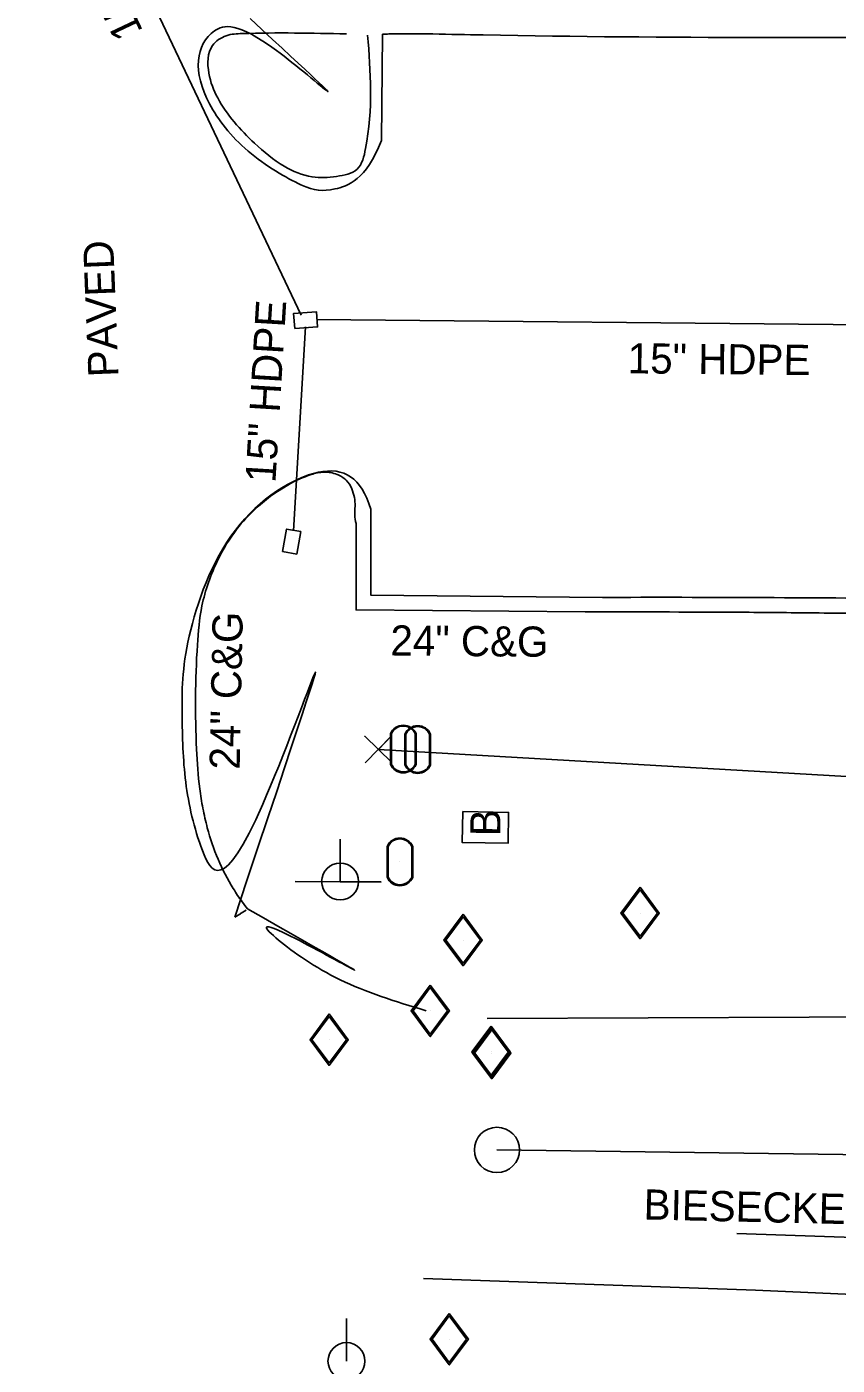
# Model space of a CAD drawing. Extents: x 1627482 to 1629573, y 760826 to 766301.
# Drawn here: x 1628089.7 to 1628197, y 764811 to 764988.4 of the extents above; entities that cross this region are included whole.
import ezdxf

# ---------------------------------------------------------------- set-up
doc = ezdxf.new("R2010")
doc.units = 0
for name, color, linetype in [('Default', 7, 'Continuous'), ('Exist Building', 7, 'Continuous'), ('Exist Building Text', 7, 'Continuous'), ('Exist Horizontal Alignment', 7, 'Continuous'), ('Exist Horizontal Alignment Point', 7, 'Continuous'), ('Exist Property Corner CELL', 7, 'Continuous'), ('Exist Right of Way Line', 7, 'Continuous'), ('Exist Roads Curbs', 7, 'Continuous'), ('Exist Roads Curbs Text', 7, 'Continuous'), ('Exist Roads EOP', 7, 'Continuous'), ('Exist Roads EOP Other', 7, 'Continuous'), ('Exist Roads EOP Text', 7, 'Continuous'), ('Exist Structure Minor Drop Inlet', 7, 'Continuous'), ('Exist Structure Minor Pipes HDPE 15 Inch', 7, 'Continuous'), ('Exist Structure Minor Pipes HDPE 15 Inch Text', 7, 'Continuous'), ('Exist Utilities Gas Valve CELL', 7, 'Continuous'), ('Exist Utilities Power Joint Use Telephone CELL', 7, 'Continuous'), ('Exist Utilities Power Pole CELL', 7, 'Continuous'), ('Exist Utilities Water Meter CELL', 7, 'Continuous'), ('Exist Utilities Water UG Line SUE LOS B', 7, 'Continuous')]:
    doc.layers.add(name, color=color, linetype=linetype)

# ---------------------------------------------------------------- blocks, each defined once
blk = doc.blocks.new('POINT_DISPLAY')
at = {"layer": 'Default'}
blk.add_line((0, 0), (0, 0), dxfattribs=at)
blk = doc.blocks.new('EXIST PROPERTY CORNER')
at = {"layer": 'Exist Property Corner CELL'}
blk.add_lwpolyline([(-3.809999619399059, -2.079104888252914e-10), (3.809999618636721, -6.930349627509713e-11), (-3.8116922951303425e-10, -2.079104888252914e-10), (-3.8116922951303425e-10, 3.8099996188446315), (-3.4651748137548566e-10, -3.8099996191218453)], dxfattribs=at)
blk.add_blockref('POINT_DISPLAY', (-3.8116922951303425e-10, -2.079104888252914e-10), dxfattribs=at)

msp = doc.modelspace()

# ---------------------------------------------------------------- linework, layer by layer
at = {"layer": 'Exist Building'}
msp.add_lwpolyline([(1628147.416, 764884.4049999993), (1628147.332230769, 764880.3054786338), (1628153.424, 764880.1809999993), (1628153.5077692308, 764884.2805213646)], close=True, dxfattribs=at)
at = {"layer": 'Exist Horizontal Alignment'}
msp.add_line((1628151.9601007, 764839.55444704), (1628347.9286044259, 764837.0098619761), dxfattribs=at)
at = {"layer": 'Exist Horizontal Alignment Point'}
msp.add_circle((1628151.9601007, 764839.55444704), 3, dxfattribs=at)
at = {"layer": 'Exist Right of Way Line'}
msp.add_lwpolyline([(1628316.1367612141, 764882.2173325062), (1628136.2421493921, 764892.6224989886)], dxfattribs=at)
at = {"layer": 'Exist Roads Curbs'}
msp.add_lwpolyline([(1628163.622, 764910.8479999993), (1628133.295, 764911.1149999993), (1628133.315, 764922.5549999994)], dxfattribs=at)
for points in [[(1628132.02, 764987.433), (1628118.222, 764987.484), (1628116.098, 764987.2000000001), (1628114.286, 764985.9180000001), (1628113.795, 764982.2170000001), (1628114.956, 764978.959), (1628119.848, 764972.947), (1628123.7480000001, 764969.898), (1628127.475, 764968.4940000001), (1628130.7040000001, 764968.558), (1628133.432, 764969.519), (1628134.551, 764972.2390000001), (1628134.824, 764987.289)], [(1628133.315, 764922.5549999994), (1628133.315, 764922.555), (1628133.155739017, 764924.853950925), (1628132.7310000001, 764927.147), (1628131.97615504, 764928.3054287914), (1628131.4102955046, 764928.735390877), (1628130.773, 764929.064), (1628129.0438645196, 764929.3706454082), (1628127.338, 764929.0480000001), (1628124.254, 764927.656), (1628119.86, 764924.414), (1628117.539, 764921.877), (1628114.955, 764917.675), (1628112.878, 764911.652), (1628112.27, 764906.471), (1628112.1570000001, 764892.64), (1628112.5772341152, 764887.4170483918), (1628112.9966976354, 764884.8213406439), (1628113.582, 764882.234), (1628115.0103715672, 764878.0750392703), (1628117.031, 764874.182), (1628118.214, 764872.4130000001), (1628118.906, 764871.5160000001)], [(1628269.175, 764910.371), (1628265.0624914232, 764910.1381060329), (1628260.9478245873, 764909.9719178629), (1628252.7204506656, 764909.7939625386), (1628236.265318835, 764909.9030827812), (1628219.8102442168, 764910.250166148), (1628203.355, 764910.593), (1628193.4221753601, 764910.7213471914), (1628183.488812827, 764910.801801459), (1628163.622, 764910.848)]]:
    msp.add_spline(points, degree=3, dxfattribs=at)
at = {"layer": 'Exist Roads EOP'}
for points in [[(1628150.643, 764856.9707), (1628193.332, 764857.133), (1628234.415, 764857.3713), (1628279.409, 764859.144), (1628289.419, 764861.2023), (1628302.9987823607, 764867.7237944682), (1628311.854, 764876.0147), (1628320.150910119, 764886.5805522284)], [(1628142.235, 764822.5291), (1628186.2280000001, 764820.9717000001), (1628230.891, 764818.9683), (1628274.652, 764816.7169), (1628294.4581179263, 764813.5617935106), (1628307.6638003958, 764807.3062263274), (1628315.974, 764801.5203), (1628323.4286103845, 764792.9474789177), (1628330.18, 764781.1492), (1628330.009, 764780.2597), (1628331.176, 764769.0084000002), (1628332.004, 764752.6177)]]:
    msp.add_lwpolyline(points, dxfattribs=at)
at = {"layer": 'Exist Roads EOP Other'}
msp.add_line((1628136.8090000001, 764987.3959999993), (1628136.654, 764973.2969999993), dxfattribs=at)
msp.add_lwpolyline([(1628165.9408687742, 764912.7661292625), (1628135.2550000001, 764913.0519999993), (1628135.235, 764924.4619999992)], dxfattribs=at)
for points in [[(1628136.654, 764973.2969999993), (1628134.628, 764968.0609999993), (1628129.739, 764966.4649999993), (1628126.911, 764966.6649999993), (1628118.441, 764971.6299999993), (1628113.251, 764978.3049999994), (1628111.798, 764984.2019999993), (1628114.026, 764988.3279999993), (1628119.266, 764989.4709999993), (1628136.654, 764973.2969999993), (1628119.266, 764989.4709999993)], [(1628135.235, 764924.4619999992), (1628133.9880000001, 764928.6819999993), (1628129.374, 764931.4219999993), (1628116.056, 764923.0979999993), (1628110.215, 764906.3789999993), (1628110.214, 764897.2549999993), (1628110.411, 764888.3449999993), (1628112.495, 764879.1489999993), (1628117.2280000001, 764870.4139999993), (1628135.235, 764924.4619999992), (1628117.2280000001, 764870.4139999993)], [(1628118.735, 764871.3099999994), (1628117.2280000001, 764870.4139999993), (1628118.735, 764871.3099999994), (1628117.2280000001, 764870.4139999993)], [(1628142.562, 764857.9979999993), (1628138.443, 764859.2249999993), (1628130.689, 764861.7249999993), (1628122.125, 764867.7459999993), (1628118.906, 764871.5159999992), (1628142.562, 764857.9979999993), (1628118.906, 764871.5159999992)]]:
    msp.add_open_spline(points, degree=3, dxfattribs=at)
for points in [[(1628267.787, 764986.6680000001), (1628256.7183733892, 764986.9814808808), (1628245.6494205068, 764987.0589539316), (1628223.511, 764987.018), (1628150.134, 764987.297), (1628143.4713701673, 764987.426266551), (1628140.140129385, 764987.4655002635), (1628138.4745478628, 764987.4486450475), (1628137.6417693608, 764987.4273341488), (1628136.8090000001, 764987.3960000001)], [(1628165.9408687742, 764912.7661292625), (1628169.68, 764912.7760000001), (1628213.124, 764912.577), (1628267.2210000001, 764912.323)]]:
    msp.add_spline(points, degree=3, dxfattribs=at)
at = {"layer": 'Exist Structure Minor Drop Inlet'}
for points in [[(1628125.1600000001, 764948.4009999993), (1628128.196240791, 764948.6099720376), (1628128.0590000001, 764950.6039999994), (1628125.0227592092, 764950.395027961)], [(1628123.5420000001, 764918.8509999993), (1628125.4286855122, 764918.5114160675), (1628125.963, 764921.4799999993), (1628124.076314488, 764921.8195839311)]]:
    msp.add_lwpolyline(points, close=True, dxfattribs=at)
at = {"layer": 'Exist Structure Minor Pipes HDPE 15 Inch'}
for p, q in [((1628082.516382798, 765041.8879629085), (1628125.9995884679, 764950.1560554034)), ((1628128.0586537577, 764949.607678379), (1628235.286423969, 764948.5760348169)), ((1628124.9800509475, 764921.5784282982), (1628126.6016877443, 764948.6013431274))]:
    msp.add_line(p, q, dxfattribs=at)
at = {"layer": 'Exist Utilities Gas Valve CELL'}
for p, q in [((1628170.92, 764870.9419999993), (1628170.92, 764870.9419999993)), ((1628147.467, 764867.3649999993), (1628147.467, 764867.3649999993)), ((1628143.122, 764857.9829999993), (1628143.122, 764857.9829999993)), ((1628129.727, 764854.1619999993), (1628129.727, 764854.1619999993)), ((1628151.187, 764852.5359999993), (1628151.187, 764852.5359999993)), ((1628151.271, 764852.3929), (1628151.271, 764852.3929)), ((1628145.644, 764814.4753), (1628145.644, 764814.4753))]:
    msp.add_line(p, q, dxfattribs=at)
for points in [[(1628170.92, 764874.3544999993), (1628168.3825, 764870.9419999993), (1628170.92, 764867.5294999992), (1628173.4575, 764870.9419999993), (1628170.92, 764874.3544999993)], [(1628147.467, 764870.7774999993), (1628144.9295, 764867.3649999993), (1628147.467, 764863.9524999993), (1628150.0045, 764867.3649999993), (1628147.467, 764870.7774999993)], [(1628143.122, 764861.3954999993), (1628140.5845, 764857.9829999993), (1628143.122, 764854.5704999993), (1628145.6595, 764857.9829999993), (1628143.122, 764861.3954999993)], [(1628129.727, 764857.5744999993), (1628127.1895, 764854.1619999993), (1628129.727, 764850.7494999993), (1628132.2645, 764854.1619999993), (1628129.727, 764857.5744999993)], [(1628151.187, 764855.9484999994), (1628148.6495, 764852.5359999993), (1628151.187, 764849.1234999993), (1628153.7245, 764852.5359999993), (1628151.187, 764855.9484999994)], [(1628151.271, 764855.8054), (1628148.7335, 764852.3929), (1628151.271, 764848.9804), (1628153.8085, 764852.3929), (1628151.271, 764855.8054)], [(1628145.644, 764817.8878000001), (1628143.1065, 764814.4753), (1628145.644, 764811.0628000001), (1628148.1815, 764814.4753), (1628145.644, 764817.8878000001)]]:
    msp.add_lwpolyline(points, dxfattribs=at)
for points in [[(1628173.2082671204, 764870.9419999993), (1628170.92, 764874.0193247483), (1628168.6317328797, 764870.9419999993), (1628170.92, 764867.8646752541)], [(1628149.7552671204, 764867.3649999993), (1628147.467, 764870.4423247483), (1628145.1787328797, 764867.3649999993), (1628147.467, 764864.2876752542)], [(1628145.4102671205, 764857.9829999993), (1628143.122, 764861.0603247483), (1628140.8337328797, 764857.9829999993), (1628143.122, 764854.9056752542)], [(1628132.0152671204, 764854.1619999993), (1628129.727, 764857.2393247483), (1628127.4387328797, 764854.1619999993), (1628129.727, 764851.0846752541)], [(1628153.4752671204, 764852.5359999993), (1628151.187, 764855.6133247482), (1628148.8987328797, 764852.5359999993), (1628151.187, 764849.4586752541)], [(1628153.5592671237, 764852.3929), (1628151.271, 764855.470224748), (1628148.9827328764, 764852.3929), (1628151.271, 764849.3155752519)], [(1628147.9322671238, 764814.4753), (1628145.644, 764817.5526247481), (1628143.3557328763, 764814.4753), (1628145.644, 764811.397975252)]]:
    msp.add_lwpolyline(points, close=True, dxfattribs=at)
at = {"layer": 'Exist Utilities Power Joint Use Telephone CELL'}
msp.add_line((1628131.182, 764875.1159999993), (1628131.182, 764875.1159999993), dxfattribs=at)
msp.add_lwpolyline([(1628125.2445, 764875.1159999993), (1628136.582, 764875.0784999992), (1628131.182, 764875.0963610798), (1628131.182, 764880.7409999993)], dxfattribs=at)
msp.add_circle((1628131.1832114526, 764875.1222499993), 2.450127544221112, dxfattribs=at)
at = {"layer": 'Exist Utilities Power Pole CELL'}
for q in [(1628132.01965705, 764817.19542524), (1628132.01965705, 764811.57042524)]:
    msp.add_line((1628132.01965705, 764811.57042524), q, dxfattribs=at)
msp.add_circle((1628132.01965705, 764811.57042524), 2.450127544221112, dxfattribs=at)
at = {"layer": 'Exist Utilities Water Meter CELL'}
for p, q in [((1628139.543, 764892.6829999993), (1628139.543, 764892.6829999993)), ((1628141.455, 764892.6179999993), (1628141.455, 764892.6179999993)), ((1628139.098, 764877.7299999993), (1628139.098, 764877.7299999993))]:
    msp.add_line(p, q, dxfattribs=at)
for points in [[(1628137.843, 764890.6454999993), (1628137.843, 764894.7204999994)], [(1628137.9805, 764890.6454999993), (1628137.9805, 764894.7204999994)], [(1628139.7550000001, 764890.5804999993), (1628139.7550000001, 764894.6554999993)], [(1628139.8925, 764890.5804999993), (1628139.8925, 764894.6554999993)], [(1628141.1055, 764894.7204999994), (1628141.1055, 764890.6204999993)], [(1628141.243, 764894.7204999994), (1628141.243, 764890.6204999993)], [(1628143.0175, 764894.6554999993), (1628143.0175, 764890.5554999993)], [(1628143.155, 764894.6554999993), (1628143.155, 764890.5554999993)], [(1628137.398, 764875.6924999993), (1628137.398, 764879.7674999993)], [(1628137.5355, 764875.6924999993), (1628137.5355, 764879.7674999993)], [(1628140.6605, 764879.7674999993), (1628140.6605, 764875.6674999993)], [(1628140.798, 764879.7674999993), (1628140.798, 764875.6674999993)]]:
    msp.add_lwpolyline(points, dxfattribs=at)
for centre, radius, start, end in [((1628139.5423214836, 764893.9756856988), 1.8560825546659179, 23.648315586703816, 156.30837593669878), ((1628141.4543214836, 764893.9106856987), 1.8560825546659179, 23.648315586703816, 156.30837593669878), ((1628139.5429999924, 764893.9876677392), 1.7258184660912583, 25.127172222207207, 154.87282777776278), ((1628141.4549999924, 764893.9226677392), 1.7258184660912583, 25.127172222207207, 154.87282777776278), ((1628139.5484609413, 764891.3756877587), 1.85520111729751, 203.1780361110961, 335.97939444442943), ((1628139.5490317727, 764891.3869728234), 1.7349564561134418, 205.3009333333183, 333.78235555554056), ((1628141.4604609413, 764891.3106877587), 1.85520111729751, 203.1780361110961, 335.97939444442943), ((1628141.4610317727, 764891.3219728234), 1.7349564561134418, 205.3009333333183, 333.78235555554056), ((1628139.0973214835, 764879.0226856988), 1.8560825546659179, 23.648315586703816, 156.30837593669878), ((1628139.0979999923, 764879.0346677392), 1.7258184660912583, 25.127172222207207, 154.87282777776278), ((1628139.1034609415, 764876.4226877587), 1.85520111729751, 203.1780361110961, 335.97939444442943), ((1628139.1040317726, 764876.4339728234), 1.7349564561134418, 205.3009333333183, 333.78235555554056)]:
    msp.add_arc(centre, radius, start, end, dxfattribs=at)
at = {"layer": 'Exist Utilities Water UG Line SUE LOS B'}
msp.add_lwpolyline([(1628183.7538, 764828.4623000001), (1628262.4598, 764825.7695), (1628297.2594, 764823.8989), (1628323.8997000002, 764822.7286), (1628355.0329000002, 764823.1733000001), (1628361.45, 764823.2226000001)], dxfattribs=at)

# ---------------------------------------------------------------- block references
at = {"layer": 'Exist Property Corner CELL', "xscale": 0.6561666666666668, "yscale": 0.6561666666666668, "rotation": 45.72460018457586}
msp.add_blockref('EXIST PROPERTY CORNER', (1628136.2421493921, 764892.622498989), dxfattribs=at)

# ---------------------------------------------------------------- texts
at = {"layer": 'Exist Building Text'}
msp.add_text('B', height=4, rotation=89.6539712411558, dxfattribs=at).set_placement((1628152.4109754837, 764881.1134028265))
at = {"layer": 'Exist Roads Curbs Text'}
for rotation, p in [(88.83831580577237, (1628117.8707265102, 764889.9162455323)), (359.4955789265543, (1628137.8301743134, 764905.0748396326))]:
    msp.add_text('24" C&G', height=4, rotation=rotation, dxfattribs=at).set_placement(p)
at = {"layer": 'Exist Roads EOP Text'}
for s, height, rotation, p in [('PAVED', 4, 92.25818983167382, (1628101.827187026, 764942.0399489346)), ('BIESECKER RD.  24" PAVED ROADWAY', 4.000000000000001, 358.6688172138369, (1628171.3552819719, 764830.345011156))]:
    msp.add_text(s, height=height, rotation=rotation, dxfattribs=at).set_placement(p)
at = {"layer": 'Exist Structure Minor Pipes HDPE 15 Inch Text'}
for height, rotation, p in [(3.999999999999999, 115.36211537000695, (1628105.1134553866, 764987.7971479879)), (4, 86.56541907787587, (1628122.6036655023, 764927.8891916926)), (4, 359.4487715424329, (1628169.2685526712, 764942.4608835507))]:
    msp.add_text('15" HDPE', height=height, rotation=rotation, dxfattribs=at).set_placement(p)

doc.saveas('drawing.dxf')
